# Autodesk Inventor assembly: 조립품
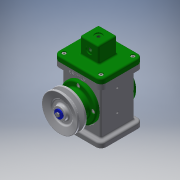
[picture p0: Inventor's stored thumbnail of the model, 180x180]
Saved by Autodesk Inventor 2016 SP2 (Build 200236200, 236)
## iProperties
Created: 2017-08
Part Number: 조립품
Document SubType Name: Assembly
Designer: Administrator
Author: Administrator
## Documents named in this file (18)
- D:\470807V1022\조립품.iam
- D:\470807V1022\본체.ipt
- D:\470807V1022\E-링.ipt
- D:\470807V1022\V-벨트풀리.ipt
- D:\470807V1022\덮개.ipt
- D:\470807V1022\뒤커버.ipt
- D:\470807V1022\링크.ipt
- D:\470807V1022\베어링 17 x 40 x 12.ipt
- D:\470807V1022\볼트 M4 x 8.ipt
- D:\470807V1022\볼트 M4 x 10.ipt
- D:\470807V1022\슬라이더.ipt
- D:\470807V1022\앞커버.ipt
- D:\470807V1022\오일 실 17 30 8.ipt
- D:\470807V1022\와셔 4x16.ipt
- D:\470807V1022\클레비스 핀 6 x 22.ipt
- 클레비스 핀 6 x 22.ipt
- D:\470807V1022\키 4 x 4 x 12.ipt
- D:\470807V1022\편심축.ipt
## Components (2 placed, 2 different names)
1. E-링:1
2. V-벨트풀리:1
